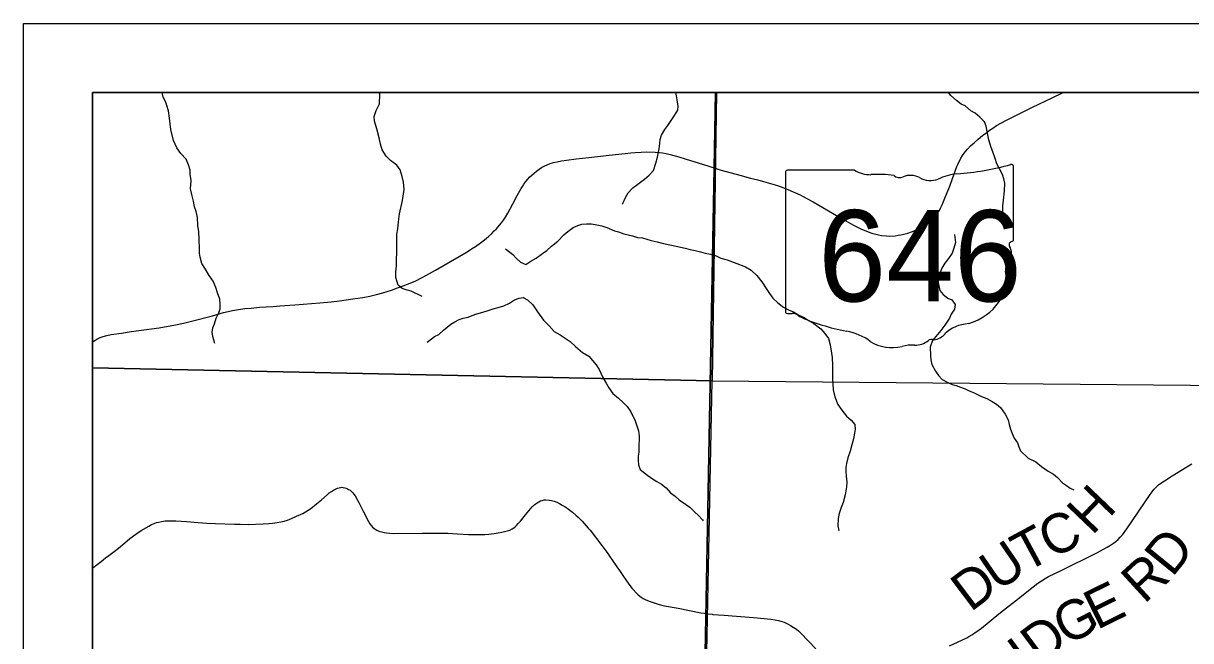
# Model space of a CAD drawing. Extents: x 0 to 34, y 0 to 22.
# Drawn here: x 10.5 to 12.186, y 19.609 to 20.5 of the extents above; entities that cross this region are included whole.
import ezdxf

# ---------------------------------------------------------------- set-up
doc = ezdxf.new("R2010")
doc.units = 0
for name, color, linetype in [('GM_X_Corporation', 7, 'Continuous'), ('GM_X_Minor_River', 7, 'Continuous'), ('GM_X_State_Location', 7, 'Continuous'), ('GM_X_State_Route', 7, 'Continuous'), ('GM_X_State_Shield', 7, 'Continuous'), ('GM_X_Township_Road', 7, 'Continuous'), ('GM_X_Township_Road_Text', 7, 'Continuous'), ('SH_Data', 7, 'Continuous')]:
    doc.layers.add(name, color=color, linetype=linetype)

msp = doc.modelspace()

# ---------------------------------------------------------------- linework, layer by layer
at = {"layer": 'GM_X_Corporation'}
for points in [[(11.5015, 20.4), (10.6, 20.4), (10.6, 20.0026), (11.4952, 19.9838)], [(11.5001, 20.4), (10.6, 20.4), (10.6, 17.5523), (10.9447, 17.5459), (11.0329, 17.5442), (11.4477, 17.5329), (11.4514, 17.7789), (11.4741, 19.003), (11.486, 19.6423), (11.498, 20.2911)], [(12.5144, 20.4), (11.5015, 20.4), (11.4952, 19.9838), (12.5051, 19.9749)], [(10.6, 20.0026), (10.6, 18.9967), (11.4752, 18.9783), (11.4952, 19.9838)], [(12.5051, 19.9749), (12.4906, 18.9558), (11.4752, 18.9783), (11.4952, 19.9838)]]:
    msp.add_lwpolyline(points, close=True, dxfattribs=at)
msp.add_lwpolyline([(16.7661, 20.4), (11.5001, 20.4), (11.498, 20.2911), (11.486, 19.6423), (11.4741, 19.003), (11.4514, 17.7789), (11.4477, 17.5329), (11.8073, 17.526), (12.504, 17.5091), (12.7693, 17.5027), (12.7967, 17.502), (13.2742, 17.4966), (14.0954, 17.4811)], dxfattribs=at)
at = {"layer": 'GM_X_Minor_River'}
for points in [[(10.7766, 20.038), (10.7736, 20.0478), (10.7728, 20.0539), (10.774, 20.0604), (10.7763, 20.0661), (10.7786, 20.0744), (10.7824, 20.082), (10.7844, 20.0877), (10.7844, 20.0949), (10.7837, 20.1018), (10.7807, 20.1109), (10.778, 20.1185), (10.7743, 20.1276), (10.7686, 20.136), (10.7622, 20.1463), (10.7581, 20.1535), (10.7555, 20.1623), (10.7547, 20.168), (10.7544, 20.1745), (10.7541, 20.1881), (10.7534, 20.1992), (10.7523, 20.2079), (10.7515, 20.2197), (10.7497, 20.2284), (10.7474, 20.2353), (10.746, 20.2433), (10.7433, 20.2528), (10.7415, 20.2612), (10.7423, 20.2729), (10.7412, 20.2824), (10.7412, 20.2881), (10.7386, 20.2957), (10.7352, 20.3037), (10.7277, 20.3121), (10.7216, 20.3201), (10.7167, 20.3308), (10.713, 20.3468), (10.7112, 20.3631), (10.7097, 20.3738), (10.7075, 20.3814), (10.7052, 20.3871), (10.7022, 20.3935), (10.7004, 20.4)], [(11.0762, 20.1057), (11.0603, 20.1132), (11.0546, 20.1147), (11.0471, 20.1174), (11.0414, 20.122), (11.038, 20.133), (11.0381, 20.1414), (11.0389, 20.1498), (11.0393, 20.1581), (11.0397, 20.1699), (11.0394, 20.1783), (11.0394, 20.1874), (11.0398, 20.1957), (11.041, 20.2033), (11.0422, 20.2132), (11.0434, 20.225), (11.048, 20.244), (11.0503, 20.2603), (11.0493, 20.2709), (11.0474, 20.2789), (11.0444, 20.2884), (11.0395, 20.2953), (11.0304, 20.3018), (11.024, 20.3083), (11.0183, 20.3174), (11.0161, 20.3254), (11.0142, 20.3349), (11.0109, 20.3479), (11.0075, 20.3589), (11.0068, 20.3657), (11.0099, 20.3741), (11.0145, 20.384), (11.0149, 20.398), (11.0143, 20.4)], [(11.3654, 20.239), (11.3701, 20.2487), (11.374, 20.2555), (11.3808, 20.2627), (11.3877, 20.268), (11.3976, 20.2748), (11.4044, 20.2809), (11.4105, 20.2877), (11.414, 20.2979), (11.4163, 20.3067), (11.4186, 20.3188), (11.4198, 20.3264), (11.4202, 20.3321), (11.4221, 20.3386), (11.4267, 20.3469), (11.4309, 20.3526), (11.4409, 20.367), (11.4458, 20.3749), (11.4459, 20.3806), (11.4448, 20.3898), (11.4436, 20.3955), (11.4425, 20.4)], [(11.9161, 20.2117), (11.9153, 20.227), (11.9153, 20.2365), (11.9161, 20.2449), (11.9173, 20.2582), (11.9181, 20.2692), (11.9166, 20.2753), (11.9148, 20.2817), (11.9102, 20.2901), (11.9065, 20.297), (11.9039, 20.305), (11.9009, 20.3145), (11.8982, 20.3206), (11.8949, 20.3316), (11.893, 20.3415), (11.8912, 20.3514), (11.8885, 20.3579), (11.8817, 20.3647), (11.8753, 20.3701), (11.8689, 20.3739), (11.8606, 20.3808), (11.8549, 20.3835), (11.8481, 20.3888), (11.8401, 20.3957), (11.8366, 20.4)], [(11.1964, 20.1745), (11.2074, 20.1662), (11.2123, 20.1604), (11.2183, 20.1551), (11.2259, 20.1516), (11.2332, 20.1566), (11.2411, 20.1611), (11.2499, 20.1675), (11.2564, 20.172), (11.2632, 20.1785), (11.272, 20.1857), (11.2807, 20.1947), (11.2868, 20.1997), (11.2945, 20.2053), (11.3013, 20.2083), (11.307, 20.2102), (11.3138, 20.2106), (11.3203, 20.2105), (11.3263, 20.2094), (11.3358, 20.2078), (11.343, 20.2051), (11.354, 20.2005), (11.3597, 20.199), (11.3676, 20.1959), (11.3737, 20.1947), (11.3802, 20.1932), (11.3873, 20.1909), (11.3946, 20.1901), (11.4071, 20.1866), (11.4158, 20.1847), (11.4249, 20.1823), (11.4362, 20.1796), (11.4434, 20.1785), (11.4495, 20.1769), (11.4563, 20.1754), (11.4635, 20.1734), (11.4707, 20.1719), (11.4783, 20.17), (11.4851, 20.1684), (11.4927, 20.1669), (11.5011, 20.1642), (11.5079, 20.1611), (11.517, 20.1584), (11.531, 20.1534), (11.5435, 20.1484), (11.5514, 20.1438), (11.5597, 20.1358), (11.5669, 20.127), (11.5741, 20.1156), (11.5782, 20.1099), (11.5827, 20.103), (11.5899, 20.0965), (11.5982, 20.0904), (11.6062, 20.0858), (11.6126, 20.0835), (11.6206, 20.0789), (11.6282, 20.0754), (11.6353, 20.0705), (11.6422, 20.0666), (11.652, 20.059), (11.658, 20.0521), (11.6633, 20.0449), (11.6659, 20.0358), (11.6678, 20.024), (11.6685, 20.0175), (11.6692, 20.0061), (11.6688, 19.9939), (11.6691, 19.9863), (11.6695, 19.9799), (11.6702, 19.9708), (11.6724, 19.9609), (11.6769, 19.9498), (11.6826, 19.9414), (11.6894, 19.933), (11.6958, 19.9273), (11.7011, 19.9208), (11.7018, 19.914), (11.7007, 19.9083), (11.6995, 19.8999), (11.6972, 19.8916), (11.6945, 19.8825), (11.691, 19.8726), (11.6891, 19.8643), (11.6883, 19.8586), (11.6883, 19.8529), (11.6886, 19.8464), (11.6897, 19.8377), (11.6893, 19.8308), (11.6874, 19.8194), (11.6843, 19.8084), (11.6816, 19.8012), (11.6785, 19.7925), (11.677, 19.7849), (11.6769, 19.7746), (11.678, 19.7678), (11.6779, 19.7682)], [(11.8455, 20.1953), (11.8468, 20.1836), (11.8445, 20.1752), (11.8418, 20.1684), (11.8364, 20.1604), (11.8315, 20.1536), (11.8269, 20.1464), (11.8234, 20.1381), (11.8223, 20.1316), (11.8219, 20.1259), (11.8241, 20.1145), (11.829, 20.1084), (11.8358, 20.1031), (11.8415, 20.1008), (11.8464, 20.0943), (11.8452, 20.0874), (11.8407, 20.0802), (11.8383, 20.0745), (11.8311, 20.0643), (11.8254, 20.0564), (11.8185, 20.0477), (11.8135, 20.042), (11.8101, 20.0325), (11.8104, 20.0203), (11.8111, 20.0142), (11.8126, 20.0074), (11.8179, 19.9979), (11.8221, 19.9914), (11.8277, 19.986), (11.8345, 19.9818), (11.8417, 19.9788), (11.8478, 19.9772), (11.8542, 19.9745), (11.8607, 19.9722), (11.8663, 19.9692), (11.8739, 19.9665), (11.8845, 19.9611), (11.8921, 19.9584), (11.8997, 19.9538), (11.9061, 19.95), (11.9118, 19.9454), (11.9186, 19.9355), (11.9227, 19.9275), (11.9242, 19.9207), (11.9264, 19.9142), (11.9287, 19.9077), (11.9317, 19.9012), (11.9362, 19.8944), (11.9381, 19.8887), (11.9407, 19.8826), (11.9517, 19.8723), (11.963, 19.8669), (11.971, 19.8604), (11.9804, 19.8535), (11.9884, 19.8489), (11.994, 19.8443), (12.0012, 19.8367), (12.0069, 19.8329), (12.0126, 19.8287), (12.0176, 19.8263)], [(11.0834, 20.0396), (11.0938, 20.0481), (11.1003, 20.0507), (11.1071, 20.0571), (11.1174, 20.0658), (11.1235, 20.0692), (11.1296, 20.0722), (11.1353, 20.0741), (11.1425, 20.076), (11.1482, 20.0783), (11.155, 20.0805), (11.1638, 20.0831), (11.1714, 20.0854), (11.179, 20.088), (11.1858, 20.0895), (11.1942, 20.0921), (11.2022, 20.0959), (11.2098, 20.1008), (11.2162, 20.1034), (11.2219, 20.1042), (11.2284, 20.1007), (11.2359, 20.0938), (11.2427, 20.0836), (11.2514, 20.0714), (11.2597, 20.0633), (11.2669, 20.0553), (11.2756, 20.0504), (11.2828, 20.0454), (11.2899, 20.0408), (11.2975, 20.0332), (11.3077, 20.0248), (11.3168, 20.0194), (11.3225, 20.0133), (11.3277, 20.0068), (11.3319, 20), (11.3368, 19.9897), (11.342, 19.9805), (11.3458, 19.9737), (11.3518, 19.9657), (11.3598, 19.9588), (11.3666, 19.9527), (11.3722, 19.9466), (11.3775, 19.939), (11.3839, 19.926), (11.3869, 19.9176), (11.3888, 19.9115), (11.3895, 19.9039), (11.3895, 19.8982), (11.3891, 19.8922), (11.389, 19.8811), (11.3883, 19.8751), (11.3882, 19.8694), (11.3886, 19.8625), (11.3912, 19.8557), (11.4003, 19.8488), (11.4075, 19.8434), (11.4154, 19.8385), (11.4218, 19.8346), (11.4287, 19.8293), (11.4351, 19.822), (11.4415, 19.8171), (11.4475, 19.8121), (11.4566, 19.806), (11.4631, 19.8014), (11.4699, 19.7949), (11.4755, 19.7896), (11.4812, 19.7831), (11.4823, 19.7817)]]:
    msp.add_lwpolyline(points, dxfattribs=at)
at = {"layer": 'GM_X_State_Route'}
for points in [[(11.508, 20.2881), (11.5351, 20.2807), (11.5507, 20.2766), (11.5612, 20.2739), (11.5695, 20.2717), (11.5795, 20.2688), (11.5894, 20.2658), (11.5972, 20.263), (11.6047, 20.2601), (11.6123, 20.2568), (11.6223, 20.2522), (11.6311, 20.2477), (11.6412, 20.2424), (11.6495, 20.2377), (11.6749, 20.2227), (11.695, 20.211), (11.7005, 20.2081), (11.711, 20.2029), (11.7174, 20.2002), (11.723, 20.1982), (11.7273, 20.1968), (11.7317, 20.1956), (11.7356, 20.1947), (11.7396, 20.1939), (11.7471, 20.1931), (11.7512, 20.1929), (11.7596, 20.1934), (11.7639, 20.194), (11.7676, 20.1946), (11.7721, 20.1956), (11.7779, 20.1972), (11.783, 20.1989), (11.7872, 20.2005), (11.7915, 20.2024), (11.7954, 20.2043), (11.7992, 20.2063), (11.8028, 20.2086), (11.8067, 20.2114), (11.8117, 20.2158), (11.8146, 20.2187), (11.8193, 20.2242), (11.8217, 20.2275), (11.8234, 20.23), (11.8252, 20.2334), (11.8274, 20.2378), (11.8325, 20.2502), (11.8385, 20.2651), (11.8425, 20.2762), (11.8488, 20.2931), (11.8501, 20.2964), (11.8545, 20.3055), (11.8567, 20.309), (11.8591, 20.3124), (11.861, 20.3149), (11.8641, 20.3184), (11.8684, 20.323), (11.8737, 20.3277), (11.8796, 20.3329), (11.8857, 20.3379), (11.8918, 20.3425), (11.8961, 20.3458), (11.9005, 20.3488), (11.906, 20.3523), (11.9197, 20.3596), (11.9302, 20.3648), (11.9579, 20.3789), (11.9862, 20.3927), (12.0013, 20.3998), (12.0017, 20.4)], [(10.6, 20.0399), (10.6007, 20.0405), (10.6033, 20.0423), (10.6063, 20.0441), (10.6108, 20.0463), (10.6154, 20.048), (10.6206, 20.0494), (10.6267, 20.0506), (10.6417, 20.0529), (10.6559, 20.0549), (10.6961, 20.0604), (10.7197, 20.0646), (10.7313, 20.0671), (10.7451, 20.0703), (10.7732, 20.0775), (10.7894, 20.0823), (10.7961, 20.0841), (10.8022, 20.0853), (10.8108, 20.0867), (10.82, 20.0881), (10.8292, 20.089), (10.841, 20.09), (10.8506, 20.0907), (10.8607, 20.0914), (10.8705, 20.092), (10.892, 20.0935), (10.9282, 20.0964), (10.9449, 20.098), (10.9569, 20.0994), (10.9761, 20.1022), (10.9903, 20.1043), (11.0004, 20.1062), (11.0102, 20.1085), (11.0193, 20.111), (11.032, 20.115), (11.0408, 20.118), (11.0489, 20.121), (11.055, 20.1234), (11.066, 20.1279), (11.0764, 20.1332), (11.0869, 20.1389), (11.0954, 20.1437), (11.1297, 20.1636), (11.141, 20.1703), (11.1476, 20.1743), (11.1532, 20.178), (11.1604, 20.1831), (11.1663, 20.1876), (11.1719, 20.1923), (11.1768, 20.1967), (11.1803, 20.2003), (11.1835, 20.2034), (11.1881, 20.2086), (11.1908, 20.2119), (11.1937, 20.2159), (11.1967, 20.2204), (11.2, 20.2259), (11.207, 20.2393), (11.2135, 20.2515), (11.2193, 20.2618), (11.221, 20.2645), (11.2232, 20.2676), (11.2261, 20.2716), (11.2289, 20.2751), (11.2318, 20.2782), (11.2345, 20.2807), (11.2379, 20.2838), (11.2415, 20.2867), (11.2452, 20.2895), (11.2487, 20.2917), (11.2532, 20.2942), (11.2566, 20.2958), (11.2609, 20.2975), (11.266, 20.299), (11.2713, 20.3002), (11.2774, 20.3014), (11.2847, 20.3025), (11.2988, 20.3043), (11.3169, 20.3063), (11.3465, 20.3095), (11.3694, 20.3121), (11.3778, 20.313), (11.3837, 20.3135), (11.3924, 20.3141), (11.401, 20.3143), (11.413, 20.3141), (11.4189, 20.3137), (11.4232, 20.3132), (11.4285, 20.3122), (11.4345, 20.3108), (11.4468, 20.3072), (11.4562, 20.3044), (11.4825, 20.2961), (11.4993, 20.2907), (11.508, 20.2881)]]:
    msp.add_lwpolyline(points, dxfattribs=at)
at = {"layer": 'GM_X_State_Shield'}
for p, q in [((11.9306, 20.1882), (11.9306, 20.2929)), ((11.601, 20.2845), (11.601, 20.0843)), ((11.7008, 20.2879), (11.6042, 20.2879)), ((11.9306, 20.1882), (11.9306, 20.1882))]:
    msp.add_line(p, q, dxfattribs=at)
for centre, major_axis, start_param, end_param in [((11.8132, 20.5607), (0.3495, 0), 4.814394, 5.042369), ((11.9269, 20.2933), (0.00367, 0), 6.141152, 7.989035), ((11.6048, 20.2849), (0.00382, 0), 1.712693, 3.28349), ((11.7238, 20.3111), (0.037, 0), 4.042523, 4.731795), ((11.736, 20.1756), (0.133, 0), 1.404758, 1.657858), ((11.7662, 20.2859), (0.0107, 0), 3.836095, 5.185415), ((11.7819, 20.2628), (0.0222, 0), 0.950623, 2.079405), ((11.8106, 20.2945), (0.0267, 0), 4.081561, 5.145723), ((11.8578, 20.2268), (0.0703, 0), 1.699011, 2.107814), ((11.9267, 20.1878), (0.00393, 0), 5.05454, 6.418171), ((11.9297, 20.1805), (0.00568, 0), 1.883978, 3.671073), ((11.8936, 20.1673), (0.0341, 0), 5.934695, 6.695948), ((11.9437, 20.1444), (0.0248, 0), 2.387724, 3.262537), ((11.8328, 20.1311), (0.0874, 0), 5.101752, 6.440018), ((11.6048, 20.0839), (0.00385, 0), 3.00124, 4.508301), ((11.6054, 20.1044), (0.0294, 0), 4.665946, 4.897461), ((11.6114, 20.0728), (0.0106, 0), 0.519207, 1.627899), ((11.7452, 20.2526), (0.2524, 0), 4.195997, 4.488961), ((11.67, 19.9944), (0.079, 0), 0.823519, 1.323587), ((11.8696, 20.0282), (0.0479, 0), 1.647645, 2.488434), ((11.7554, 20.0718), (0.0501, 0), 4.026481, 4.996735), ((11.7844, 20.0026), (0.0412, 0), 1.495662, 1.94098), ((11.788, 20.0568), (0.0267, 0), 4.691044, 5.507374), ((11.8122, 20.0374), (0.00752, 0), 1.147584, 2.315152), ((11.809, 20.065), (0.0282, 0), 4.937069, 5.64225)]:
    msp.add_ellipse(centre, major_axis=major_axis, ratio=0.8, start_param=start_param, end_param=end_param, dxfattribs=at)
at = {"layer": 'GM_X_Township_Road'}
for points in [[(11.838, 19.6011), (11.8558, 19.6094), (11.8632, 19.6129), (11.8661, 19.6145), (11.8702, 19.6169), (11.8749, 19.62), (11.8796, 19.6234), (11.8841, 19.6269), (11.9092, 19.6473), (11.9159, 19.6525), (11.942, 19.6729), (11.952, 19.6812), (11.9588, 19.6866), (11.9659, 19.6918), (11.9709, 19.6953), (11.9761, 19.6985), (11.9812, 19.7012), (11.9985, 19.7097), (12.0521, 19.7358), (12.0608, 19.7406), (12.066, 19.7435), (12.0707, 19.7464), (12.075, 19.7493), (12.0783, 19.7519), (12.0817, 19.755), (12.0848, 19.7582), (12.0879, 19.7616), (12.0905, 19.7649), (12.0943, 19.77), (12.1282, 19.8198), (12.1309, 19.8235), (12.1333, 19.8268), (12.1364, 19.83), (12.1402, 19.8336), (12.1448, 19.837), (12.1486, 19.8395), (12.1597, 19.8465), (12.181, 19.8596), (12.1883, 19.8641)], [(10.6, 19.7132), (10.6046, 19.717), (10.6125, 19.7231), (10.6187, 19.7282), (10.6235, 19.7315), (10.6313, 19.7376), (10.6375, 19.7423), (10.6464, 19.75), (10.654, 19.756), (10.6624, 19.7624), (10.6703, 19.7677), (10.6812, 19.774), (10.6838, 19.7755), (10.6864, 19.7768), (10.6889, 19.7779), (10.6923, 19.7791), (10.6957, 19.78), (10.7002, 19.7809), (10.7047, 19.7815), (10.7088, 19.7818), (10.7128, 19.7819), (10.7202, 19.7818), (10.7356, 19.7807), (10.7527, 19.7791), (10.7649, 19.7783), (10.7776, 19.7779), (10.8049, 19.7769), (10.8133, 19.7767), (10.8246, 19.7765), (10.8465, 19.7773), (10.8545, 19.7778), (10.8599, 19.7783), (10.8667, 19.7791), (10.872, 19.7801), (10.8769, 19.7814), (10.8816, 19.7829), (10.8873, 19.7852), (10.8946, 19.7883), (10.9002, 19.7907), (10.9037, 19.7925), (10.9078, 19.7947), (10.9117, 19.7969), (10.9153, 19.7995), (10.9236, 19.8061), (10.9308, 19.812), (10.9389, 19.8193), (10.9419, 19.822), (10.945, 19.824), (10.9479, 19.8259), (10.9511, 19.8276), (10.9538, 19.8289), (10.9561, 19.8296), (10.9583, 19.83), (10.9603, 19.8301), (10.9622, 19.83), (10.9645, 19.8295), (10.9662, 19.8289), (10.9682, 19.8281), (10.97, 19.8271), (10.9721, 19.8258), (10.974, 19.824), (10.9759, 19.8221), (10.9774, 19.8202), (10.9792, 19.8179), (10.9829, 19.8117), (10.9848, 19.8083), (10.991, 19.7959), (10.9986, 19.7807), (11.0006, 19.7776), (11.003, 19.7744), (11.0045, 19.7726), (11.0065, 19.771), (11.0085, 19.7695), (11.0105, 19.7683), (11.0125, 19.7674), (11.015, 19.7665), (11.0178, 19.7657), (11.0215, 19.7648), (11.0245, 19.7643), (11.0288, 19.7638), (11.0342, 19.7636), (11.0764, 19.7638), (11.1132, 19.764), (11.12, 19.7635), (11.1272, 19.763), (11.1432, 19.7618), (11.1621, 19.7618), (11.1669, 19.7621), (11.1724, 19.7625), (11.18, 19.7634), (11.1861, 19.7642), (11.1914, 19.7652), (11.1951, 19.7661), (11.1989, 19.7671), (11.2027, 19.7684), (11.2061, 19.77), (11.21, 19.7727), (11.2125, 19.7751), (11.2151, 19.778), (11.2181, 19.7812), (11.2257, 19.7906), (11.235, 19.8018), (11.2369, 19.8037), (11.2397, 19.8058), (11.2422, 19.8076), (11.2447, 19.8093), (11.2471, 19.8105), (11.2496, 19.8113), (11.2524, 19.8118), (11.2549, 19.8119), (11.2598, 19.8116), (11.263, 19.8111), (11.2667, 19.8101), (11.2707, 19.8086), (11.2744, 19.8068), (11.2786, 19.8045), (11.2822, 19.8022), (11.2874, 19.7985), (11.2933, 19.794), (11.2982, 19.7901), (11.3014, 19.7872), (11.3075, 19.7811), (11.3103, 19.7781), (11.3162, 19.7712), (11.3187, 19.768), (11.3358, 19.7459), (11.3445, 19.7344), (11.347, 19.7308), (11.3504, 19.7259), (11.3576, 19.7153), (11.3613, 19.7098), (11.367, 19.7015), (11.3738, 19.6916), (11.3791, 19.6846), (11.3874, 19.6758), (11.388, 19.6752)], [(11.388, 19.6752), (11.3885, 19.6747), (11.3905, 19.673), (11.3928, 19.6715), (11.3957, 19.6698), (11.3985, 19.6682), (11.4016, 19.6668), (11.4055, 19.6652), (11.4158, 19.6618), (11.4205, 19.6605), (11.4264, 19.6591), (11.4459, 19.6554), (11.4787, 19.649), (11.4838, 19.6483), (11.4893, 19.6475), (11.4953, 19.6468), (11.4963, 19.6467)], [(11.4963, 19.6467), (11.5125, 19.6453), (11.524, 19.6444), (11.5367, 19.6434), (11.5551, 19.6421), (11.5703, 19.6409), (11.58, 19.6398), (11.5863, 19.6388), (11.5909, 19.6379), (11.5958, 19.6366), (11.599, 19.6354), (11.602, 19.6341), (11.6051, 19.6326), (11.6084, 19.6308), (11.6124, 19.6282), (11.6169, 19.6251), (11.6197, 19.6227), (11.6231, 19.6195), (11.6451, 19.597)]]:
    msp.add_lwpolyline(points, dxfattribs=at)
at = {"layer": 'SH_Data'}
for points in [[(10.5, 20.5), (17.5, 20.5), (17.5, 13.5), (10.5, 13.5)], [(10.6, 20.4), (17.4, 20.4), (17.4, 13.6), (10.6, 13.6)]]:
    msp.add_lwpolyline(points, close=True, dxfattribs=at)

# ---------------------------------------------------------------- texts
at = {"layer": 'GM_X_State_Location'}
for s in ['s', 'r']:
    msp.add_text(s, height=0.000189, dxfattribs=at).set_placement((11.7621, 20.1711))
msp.add_text('646', height=0.000189, rotation=0, dxfattribs=at).set_placement((11.6952, 20.1573))
at = {"layer": 'GM_X_State_Shield'}
msp.add_text('646', height=0.13184, dxfattribs=at).set_placement((11.6484, 20.0985))
at = {"layer": 'GM_X_Township_Road_Text'}
for s, rotation, p in [('H', 46.3082, (12.0441, 19.7595)), ('C', 25.9855, (11.9845, 19.7261)), ('T', 28.2691, (11.9476, 19.7062)), ('U', 34.4883, (11.9078, 19.6788)), ('D', 51.0164, (12.1598, 19.699)), ('D', 37.0382, (11.8684, 19.6491)), ('R', 42.5441, (12.1192, 19.6607)), ('E', 26.1491, (12.051, 19.6237)), ('G', 27.1075, (12.0067, 19.601)), ('D', 36.7752, (11.9688, 19.5724)), ('I', 36.2579, (11.9496, 19.5583))]:
    msp.add_text(s, height=0.0568, rotation=rotation, dxfattribs=at).set_placement(p)

doc.saveas('drawing.dxf')
